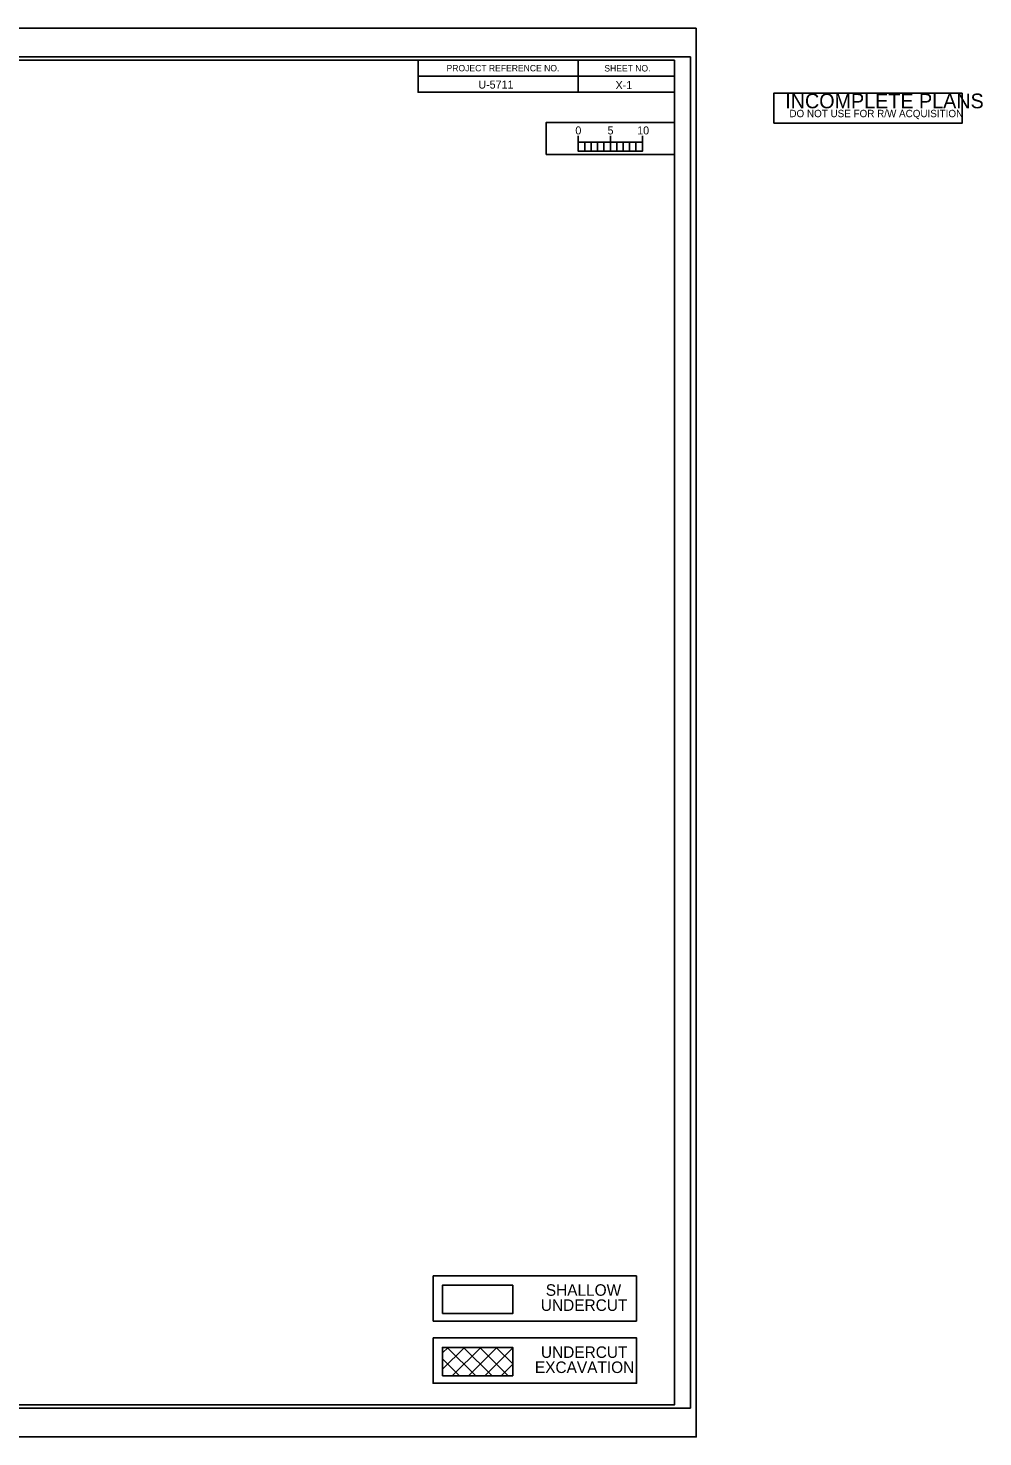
# Model space of a CAD drawing. Extents: x -19 to 363, y -37 to 220.
# Drawn here: x 213.6 to 362.6, y 0 to 220 of the extents above; entities that cross this region are included whole.
import ezdxf

# ---------------------------------------------------------------- set-up
doc = ezdxf.new("R2010")
doc.units = 0
for name, color, linetype in [('Old_Level_2', 7, 'Continuous'), ('Old_Level_38', 7, 'Continuous'), ('Old_Level_40', 7, 'Continuous'), ('Old_Level_41', 7, 'Continuous'), ('Prop Grid Mask', 7, 'Continuous'), ('Prop Shade Light', 7, 'Continuous'), ('Prop XS Sheet Number', 7, 'Continuous'), ('Prop XS Undercut Exc Hatch', 7, 'Continuous'), ('Prop XSC Text', 7, 'Continuous'), ('Sheet Cutting Line CELL', 7, 'Continuous'), ('Sheet Plot Border Inside CELL', 7, 'Continuous'), ('Sheet Plot Border Outside CELL', 7, 'Continuous'), ('Sheet Sticker Incomplete CELL', 7, 'Continuous'), ('Sheet Typical CELL', 7, 'Continuous')]:
    doc.layers.add(name, color=color, linetype=linetype)

msp = doc.modelspace()

# ---------------------------------------------------------------- linework, layer by layer
at = {"layer": 'Old_Level_2'}
msp.add_lwpolyline([(278.24, 19.25), (289.22, 19.25), (289.22, 23.69), (278.24, 23.69)], close=True, dxfattribs=at)
at = {"layer": 'Old_Level_38'}
for p, q in [((299.45, 200.79), (299.45, 203.2)), ((299.45, 202.2), (299.45, 203.2)), ((304.45, 200.79), (304.45, 203.2)), ((309.45, 200.79), (309.45, 203.2)), ((309.45, 202.2), (309.45, 203.2))]:
    msp.add_line(p, q, dxfattribs=at)
for points in [[(309.45, 202.2), (299.45, 202.2), (299.45, 200.79), (309.45, 200.79)], [(299.45, 202.2), (300.45, 202.2), (300.45, 200.79), (299.45, 200.79)], [(301.45, 202.2), (302.45, 202.2), (302.45, 200.79), (301.45, 200.79)], [(303.45, 202.2), (304.45, 202.2), (304.45, 200.79), (303.45, 200.79)], [(305.45, 202.2), (306.45, 202.2), (306.45, 200.79), (305.45, 200.79)], [(307.45, 202.2), (308.45, 202.2), (308.45, 200.79), (307.45, 200.79)]]:
    msp.add_lwpolyline(points, close=True, dxfattribs=at)
at = {"layer": 'Old_Level_40'}
msp.add_line((314.45, 202.8), (314.45, 200.3), dxfattribs=at)
msp.add_lwpolyline([(314.45, 205.3), (294.45, 205.3), (294.45, 200.3), (314.45, 200.3)], close=True, dxfattribs=at)
at = {"layer": 'Old_Level_41'}
msp.add_line((294.45, 205.3), (294.45, 200.33), dxfattribs=at)
at = {"layer": 'Prop Grid Mask'}
for p, q in [((276.77, 25.16), (308.55, 25.16)), ((276.77, 18.08), (276.77, 25.16)), ((308.55, 25.16), (308.55, 18.08)), ((308.55, 18.08), (276.77, 18.08))]:
    msp.add_line(p, q, dxfattribs=at)
for points in [[(276.77, 15.46), (308.55, 15.46), (308.55, 8.38), (276.77, 8.38)], [(278.24, 9.55), (289.22, 9.55), (289.22, 13.99), (278.24, 13.99)]]:
    msp.add_lwpolyline(points, close=True, dxfattribs=at)
at = {"layer": 'Prop Shade Light'}
for p, q in [((278.24, 23.69), (278.24, 19.36)), ((289.18, 23.69), (278.24, 23.69)), ((289.22, 23.65), (289.18, 23.69)), ((278.24, 19.36), (278.34, 19.25))]:
    msp.add_line(p, q, dxfattribs=at)
msp.add_lwpolyline([(278.34, 19.25), (289.22, 19.25), (289.22, 23.65)], dxfattribs=at)
at = {"layer": 'Prop XS Undercut Exc Hatch'}
for p, q in [((278.24, 13.11), (279.12, 13.99)), ((278.24, 10.56), (281.66, 13.99)), ((278.99, 13.99), (283.43, 9.55)), ((279.77, 9.55), (284.21, 13.99)), ((281.54, 13.99), (285.98, 9.55)), ((282.31, 9.55), (286.75, 13.99)), ((284.08, 13.99), (288.52, 9.55)), ((284.86, 9.55), (289.22, 13.91)), ((286.63, 13.99), (289.22, 11.4)), ((289.18, 13.99), (289.22, 13.95)), ((278.24, 12.2), (280.89, 9.55)), ((287.4, 9.55), (289.22, 11.36)), ((278.24, 9.65), (278.34, 9.55))]:
    msp.add_line(p, q, dxfattribs=at)
at = {"layer": 'Sheet Cutting Line CELL'}
for p, q in [((317.85, 220.01), (-18.95, 220.01)), ((-18.95, 0.01), (317.85, 0.01))]:
    msp.add_line(p, q, dxfattribs=at)
at = {"layer": 'Sheet Plot Border Inside CELL'}
msp.add_lwpolyline([(316.95, 215.52), (-16.35, 215.52), (-16.35, 4.5), (316.95, 4.5)], close=True, dxfattribs=at)
at = {"layer": 'Sheet Plot Border Outside CELL'}
msp.add_lwpolyline([(317.85, 220.01), (-18.95, 220.01), (-18.95, 0.01), (317.85, 0.01)], close=True, dxfattribs=at)
at = {"layer": 'Sheet Sticker Incomplete CELL'}
msp.add_lwpolyline([(329.97, 205.16), (329.97, 209.86), (359.37, 209.86), (359.37, 205.16)], close=True, dxfattribs=at)
at = {"layer": 'Sheet Typical CELL'}
for p, q in [((299.45, 215), (299.45, 210)), ((274.44, 212.5), (314.45, 212.5))]:
    msp.add_line(p, q, dxfattribs=at)
for points in [[(314.45, 215.01), (14.45, 215.01), (14.45, 5.01), (314.45, 5.01)], [(274.44, 215.01), (314.45, 215.01), (314.45, 210), (274.44, 210)]]:
    msp.add_lwpolyline(points, close=True, dxfattribs=at)

# ---------------------------------------------------------------- texts
at = {"layer": 'Old_Level_38'}
for s, p in [('0', (298.99, 203.42)), ('5', (304.01, 203.42)), ('10', (308.64, 203.42))]:
    msp.add_text(s, height=1.25, dxfattribs=at).set_placement(p)
at = {"layer": 'Old_Level_40'}
msp.add_text('U-5711', height=1.25, dxfattribs=at).set_placement((283.84, 210.58))
at = {"layer": 'Prop XS Sheet Number'}
msp.add_text('X-1', height=1.25, dxfattribs=at).set_placement((305.26, 210.5))
at = {"layer": 'Prop XSC Text'}
for s, p in [('SHALLOW', (294.37, 22.04)), ('UNDERCUT', (293.6, 19.68)), ('UNDERCUT', (293.61, 12.34)), ('EXCAVATION', (292.67, 9.98))]:
    msp.add_text(s, height=1.8, dxfattribs=at).set_placement(p)
at = {"layer": 'Sheet Sticker Incomplete CELL'}
for s, height, p in [('INCOMPLETE PLANS', 2.304, (331.76, 207.5)), ('DO NOT USE FOR R/W ACQUISITION', 1.152, (332.41, 206.11))]:
    msp.add_text(s, height=height, dxfattribs=at).set_placement(p)
at = {"layer": 'Sheet Typical CELL'}
for s, p in [('PROJECT REFERENCE NO.', (278.88, 213.27)), ('SHEET NO.', (303.51, 213.25))]:
    msp.add_text(s, height=1, dxfattribs=at).set_placement(p)

doc.saveas('drawing.dxf')
